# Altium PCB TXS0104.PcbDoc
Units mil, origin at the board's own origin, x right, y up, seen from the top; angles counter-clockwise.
Board outline 6000 x 4000 mil, 2 copper layers (Top Layer, Bottom Layer); 8 components, 12 nets, 43 pads, 0 vias.
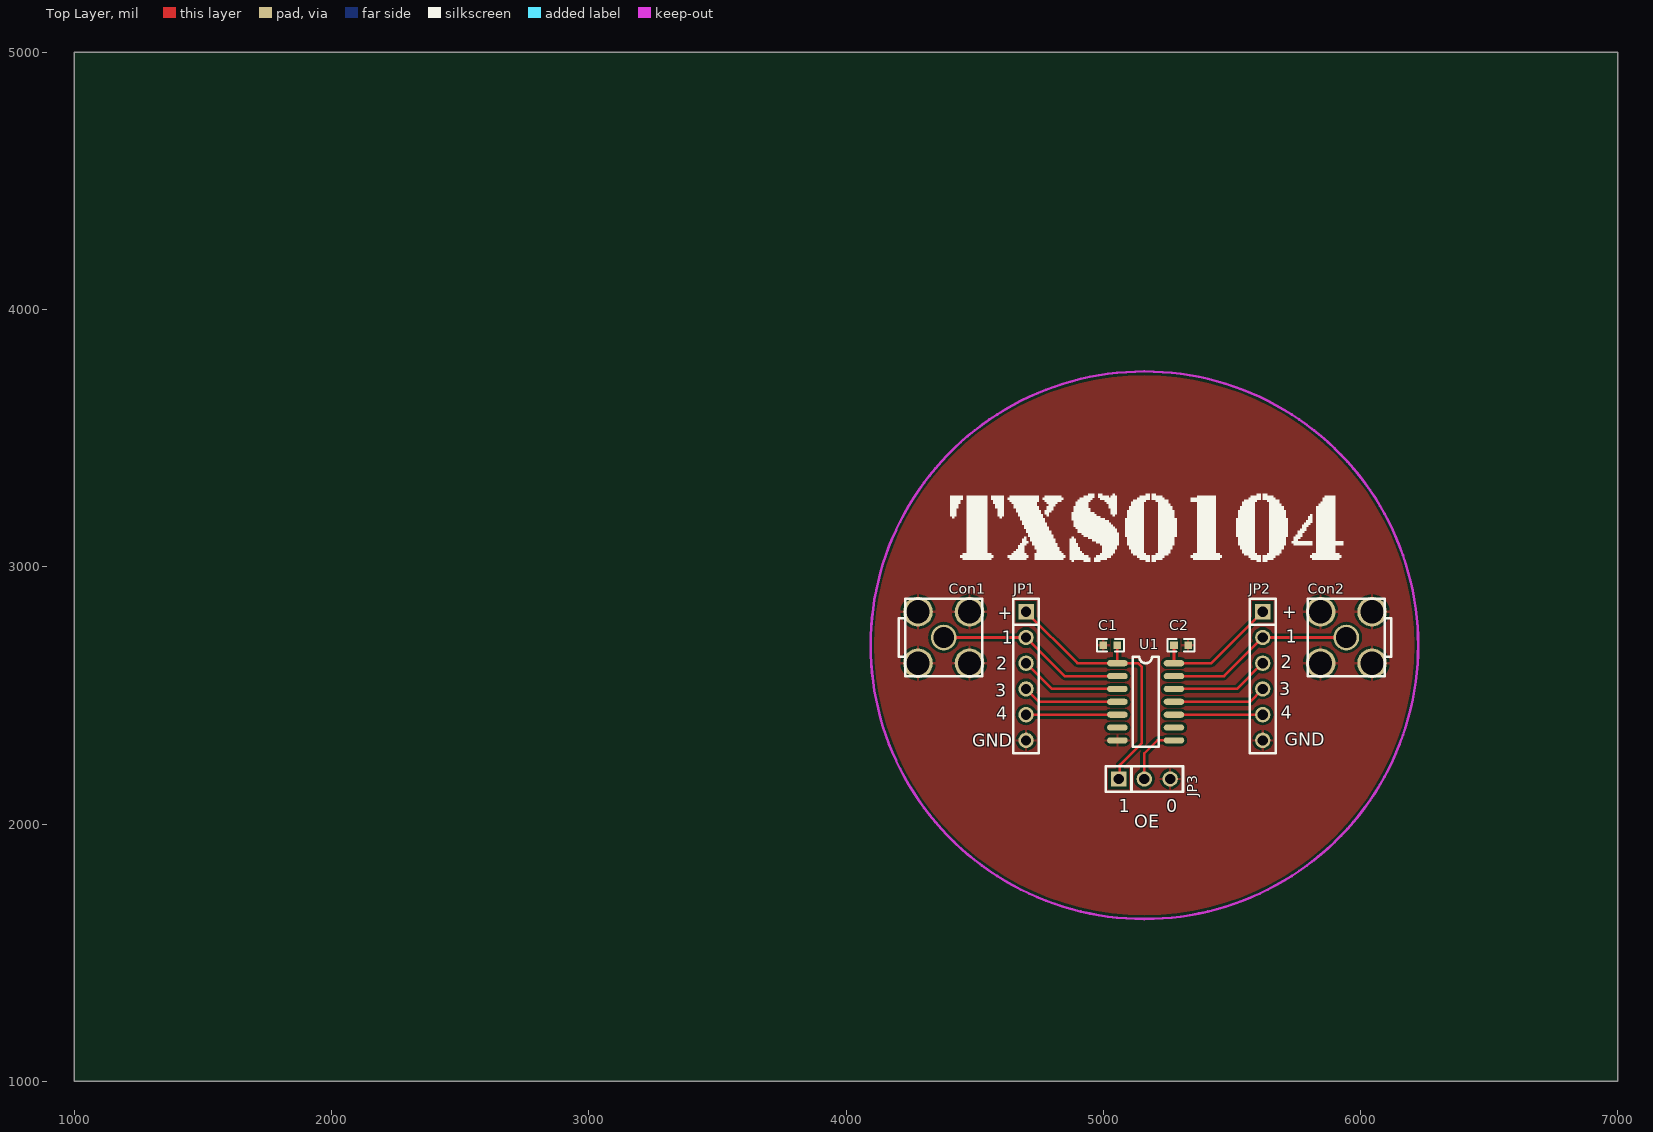
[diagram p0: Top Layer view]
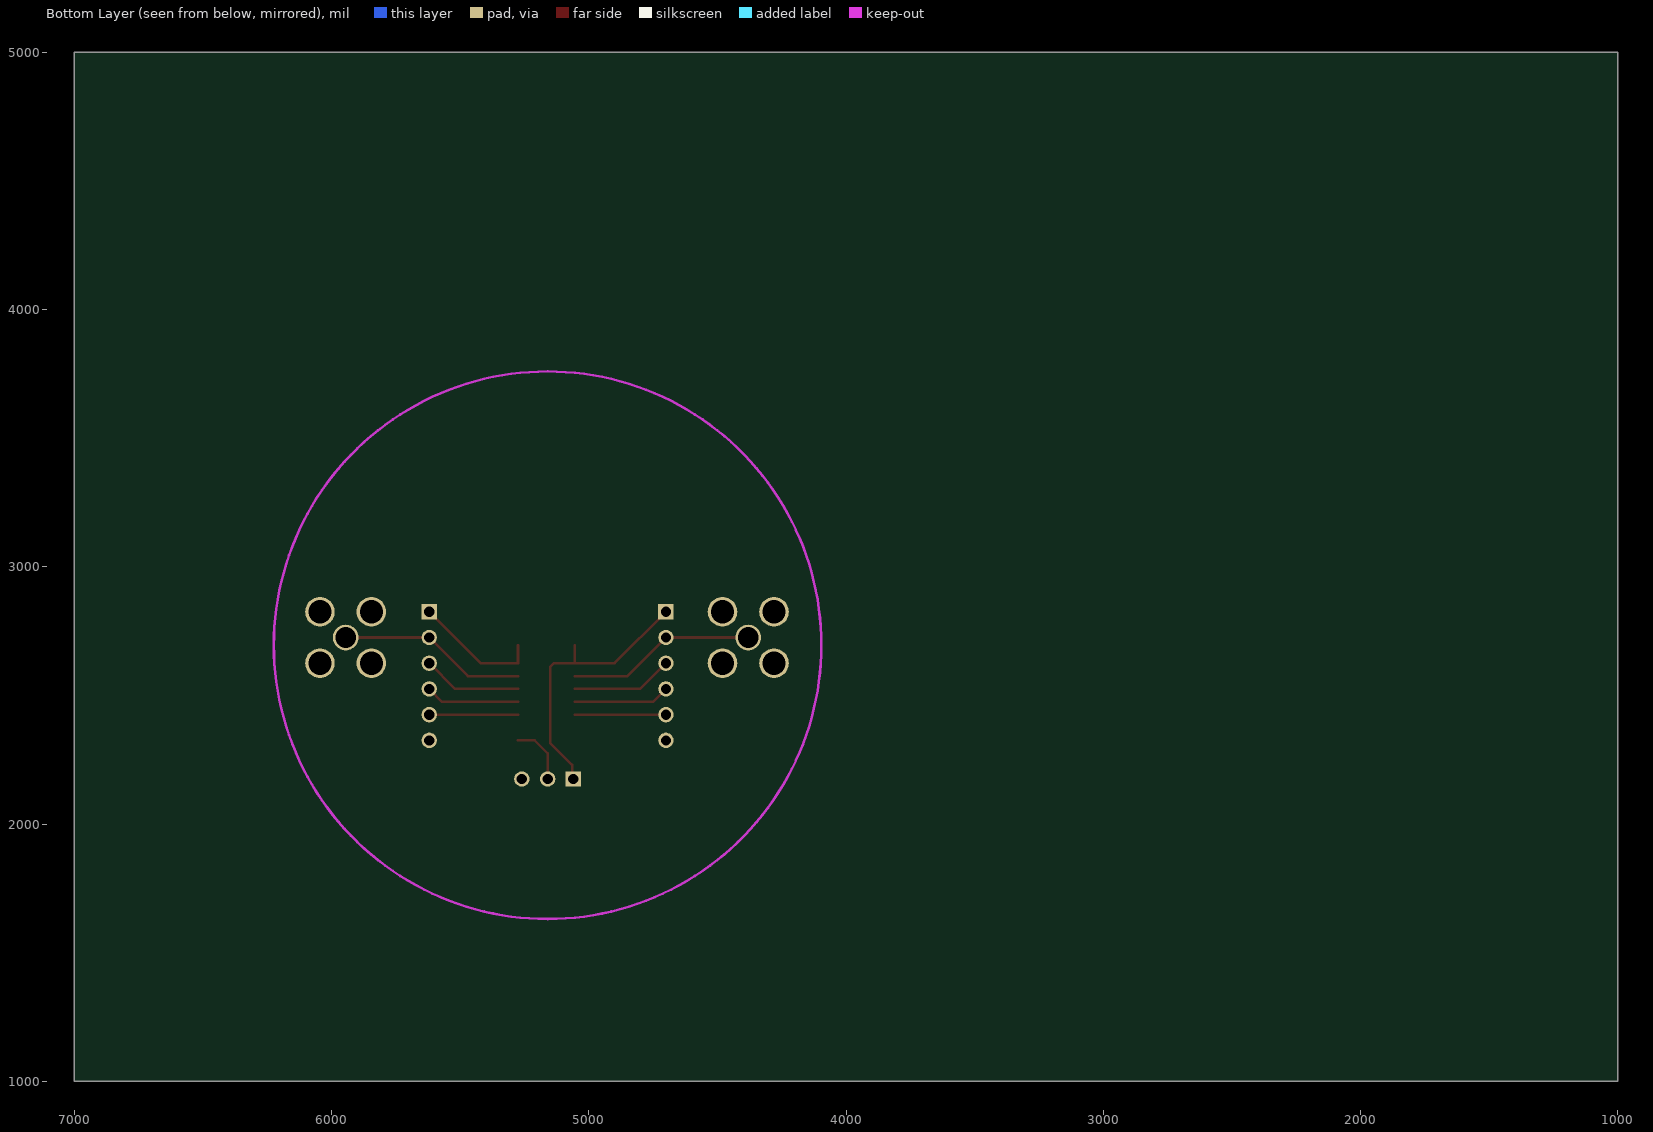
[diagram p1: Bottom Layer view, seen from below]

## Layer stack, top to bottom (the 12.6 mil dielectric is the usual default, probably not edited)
Top Solder: solder mask 0.4, Solder Resist, Dk 3.5
Top Layer: signal copper 1.4
Dielectric 1: dielectric 12.6, FR-4, Dk 4.8
Bottom Layer: signal copper 1.4
Bottom Solder: solder mask 0.4, Solder Resist, Dk 3.5

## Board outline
1000,1000 7000,1000 7000,5000 1000,5000

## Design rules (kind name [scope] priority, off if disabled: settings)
Clearance [All] p1: gap=10
PolygonConnect [All] p1: connectstyle=Relief reliefconductorwidth=10 reliefentries=4 polygonreliefangle="90 Angle" airgapwidth=10
RoutingVias [All] p1: holewidth=28 width=50 viastyle="Through Hole" minholewidth=28 minwidth=50 maxholewidth=28 maxwidth=50
SolderMaskExpansion [All] p1: expansion=4
Width [All] p1: maxlimit=10 minlimit=10 preferedwidth=10
29 further rules are at their usual default settings.

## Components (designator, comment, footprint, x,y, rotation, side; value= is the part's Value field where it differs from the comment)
C1 "100nF" 0603 5055,2695 r180 top
C2 "100nF" 0603 5275,2695 r0 top
Con1 "In" SMB_90 4380,2725 r180 top
Con2 "In" SMB_90 5945,2725 r0 top
JP1 "HEADER 6" SIP-6 4700,2825 r270 top
JP2 "HEADER 6" SIP-6 5620,2825 r270 top
JP3 "JP" sip-3 5060,2175 r0 top
U1 "TXS0104EDR" SO14 5055,2625 r0 top

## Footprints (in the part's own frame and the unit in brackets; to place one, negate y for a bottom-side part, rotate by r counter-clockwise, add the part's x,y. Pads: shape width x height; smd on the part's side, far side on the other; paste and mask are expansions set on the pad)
0603 [mil]
  rect 30x30 smd: 1(0,0) 2(55,0)
  silkscreen extent -25,-25 80,25
sip-3 [mil]
  rect 60x60 hole 40: 1(0,0)
  round 60 hole 40: 2(100,0) 3(200,0)
  silkscreen extent -50,-50 250,50
SIP-6 [mil]
  rect 60x60 hole 40: 1(0,0)
  round 60 hole 40: 2(100,0) 3(200,0) 4(300,0) 5(400,0) 6(500,0)
  silkscreen extent -50,-50 550,50
SMB_90 [mil]
  round 100 hole 80: 1(0,0)
  round 115 hole 90: 2(-100,100) 2(-100,-100) 2(100,100) 2(100,-100)
  silkscreen extent -150,-150 175,150
SO14 [mil]
  oval 80x24 smd: 1(0,0) 2(0,-50) 3(0,-100) 4(0,-150) 5(0,-200) 6(0,-250) 7(0,-300) 8(220,-300) 9(220,-250) 10(220,-200) 11(220,-150) 12(220,-100) 13(220,-50) 14(220,0)
  silkscreen extent 60,-325 160,25

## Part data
C1 C2: library part CAP, "Capacitor"
Con1 Con2: library part SMB
JP3: "Jumper"
U1: library part TXS0104

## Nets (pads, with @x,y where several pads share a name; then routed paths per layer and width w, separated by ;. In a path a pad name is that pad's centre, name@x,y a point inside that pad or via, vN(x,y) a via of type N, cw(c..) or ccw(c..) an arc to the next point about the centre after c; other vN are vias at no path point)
A1: Con1.1 JP1.2 U1.2 | length 737.1
  Top Layer w10: Con1.1 JP1.2 4850,2575 U1.2
B1: Con2.1 JP2.2 U1.13 | length 732.1
  Top Layer w10: U1.13 5470,2575 JP2.2 Con2.1
GND: C1.2 C2.2 Con1.2 Con2.2 JP1.6 JP2.6 JP3.3 U1.7
NetJP1_3: JP1.3 U1.3 | length 396.4
  Top Layer w10: JP1.3 4800,2525 U1.3
NetJP1_4: JP1.4 U1.4 | length 375.7
  Top Layer w10: JP1.4 4750,2475 U1.4
NetJP1_5: JP1.5 U1.5 | length 355
  Top Layer w10: JP1.5 U1.5
NetJP2_3: JP2.3 U1.12 | length 386.4
  Top Layer w10: U1.12 5520,2525 JP2.3
NetJP2_4: JP2.4 U1.11 | length 365.7
  Top Layer w10: U1.11 5570,2475 JP2.4
NetJP2_5: JP2.5 U1.10 | length 345
  Top Layer w10: U1.10 JP2.5
NetJP3_2: JP3.2 U1.8 | length 235.7
  Top Layer w10: JP3.2 5160,2275 5210,2325 U1.8
VCCA: C1.1 JP1.1 JP3.1 U1.1 | length 1084.3
  Top Layer w10: JP1.1 4900,2625 U1.1 ; C1.1 U1.1 ; JP3.1 5065,2175 5065,2230 5150,2315 5150,2610 5135,2625 U1.1
VCCB: C2.1 JP2.1 U1.14 | length 497.8
  Top Layer w10: C2.1 U1.14 5420,2625 JP2.1
pads on no net: U1.6 U1.9

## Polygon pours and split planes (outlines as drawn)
GND on Top Layer "Bottom Layer-No Net" (solid, remove dead copper, pour order 5): 4235,3255 4235,3270 4595,3630 4745,3780 5140,3780 5590,3780 6180,3190 6240,3130 6240,2500 6240,2260 5600,1620 5590,1610 5120,1610 4730,1610 4255,2085 4075,2265 4075,2835 4075,3110 4240,3275

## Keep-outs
Keep-Out Layer:
  circle w10: c5160,2695 r1064.25

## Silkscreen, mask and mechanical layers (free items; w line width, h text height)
Top Overlay:
  drawing of 16 lines, arcs and shapes, not listed
  text "+" at 5695,2800 h50
  text "+" at 4590,2795 h50
  text "1" at 5710,2705 h50
  text "1" at 4605,2700 h50
  text "2" at 5690,2605 h50
  text "2" at 4585,2600 h50
  text "3" at 5685,2500 h50
  text "3" at 4580,2495 h50
  text "4" at 5690,2410 h50
  text "4" at 4585,2405 h50
  text "GND" at 5705,2305 h50
  text "GND" at 4490,2300 h50
  text "1" at 5060,2045 h50
  text "0" at 5245,2045 h50
  text "OE" at 5120,1985 h50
